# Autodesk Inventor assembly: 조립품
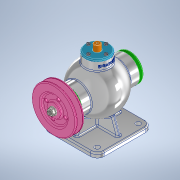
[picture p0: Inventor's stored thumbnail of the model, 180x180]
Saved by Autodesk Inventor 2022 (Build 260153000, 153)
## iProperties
Created: 2024-04
Part Number: 조립품
Document SubType Name: Assembly
Designer: Admin
Author: Admin
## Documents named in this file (16)
- C:\Users\Admin\Desktop\740406V1015\조립품.iam
- C:\Users\Admin\Desktop\740406V1015\본체.ipt
- C:\Users\Admin\Desktop\740406V1015\뒤커버.ipt
- C:\Users\Admin\Desktop\740406V1015\앞커버.ipt
- C:\Users\Admin\Desktop\740406V1015\상부커버.ipt
- C:\Users\Admin\Desktop\740406V1015\베어링- 6202.ipt
- KS B 2023 - 6202 - 15 x 35 x 11 - 7.8.ipt
- C:\Users\Admin\Desktop\740406V1015\칼라.ipt
- C:\Users\Admin\Desktop\740406V1015\편심축.ipt
- C:\Users\Admin\Desktop\740406V1015\키 4 x 4 x 12.ipt
- C:\Users\Admin\Desktop\740406V1015\오일실 15 30 7.ipt
- C:\Users\Admin\Desktop\740406V1015\V-벨트풀리.ipt
- C:\Users\Admin\Desktop\740406V1015\볼트 M4 x 16.ipt
- C:\Users\Admin\Desktop\740406V1015\볼트 M4 x 12.ipt
- C:\Users\Admin\Desktop\740406V1015\슬라이드.ipt
- C:\Users\Admin\Desktop\740406V1015\너트 M8.ipt
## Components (15 placed, 4 different names)
1. KS B 2023 - 6202 - 15 x 35 x 11 - 7.8:1
2. KS B 2023 - 6202 - 15 x 35 x 11 - 7.8:2
3. V-벨트풀리:1
4. ISO 4762 M4 x 16:1
5. ISO 4762 M4 x 16:2
6. ISO 4762 M4 x 16:3
7. ISO 4762 M4 x 16:4
8. ISO 4762 M4 x 16:5
9. ISO 4762 M4 x 16:6
10. ISO 4762 M4 x 16:7
11. ISO 4762 M4 x 16:8
12. KS B 1021 - 에 따름 ISO 1207 - 미터 A  M 4 x 12:1
13. KS B 1021 - 에 따름 ISO 1207 - 미터 A  M 4 x 12:2
14. KS B 1021 - 에 따름 ISO 1207 - 미터 A  M 4 x 12:3
15. KS B 1021 - 에 따름 ISO 1207 - 미터 A  M 4 x 12:4
